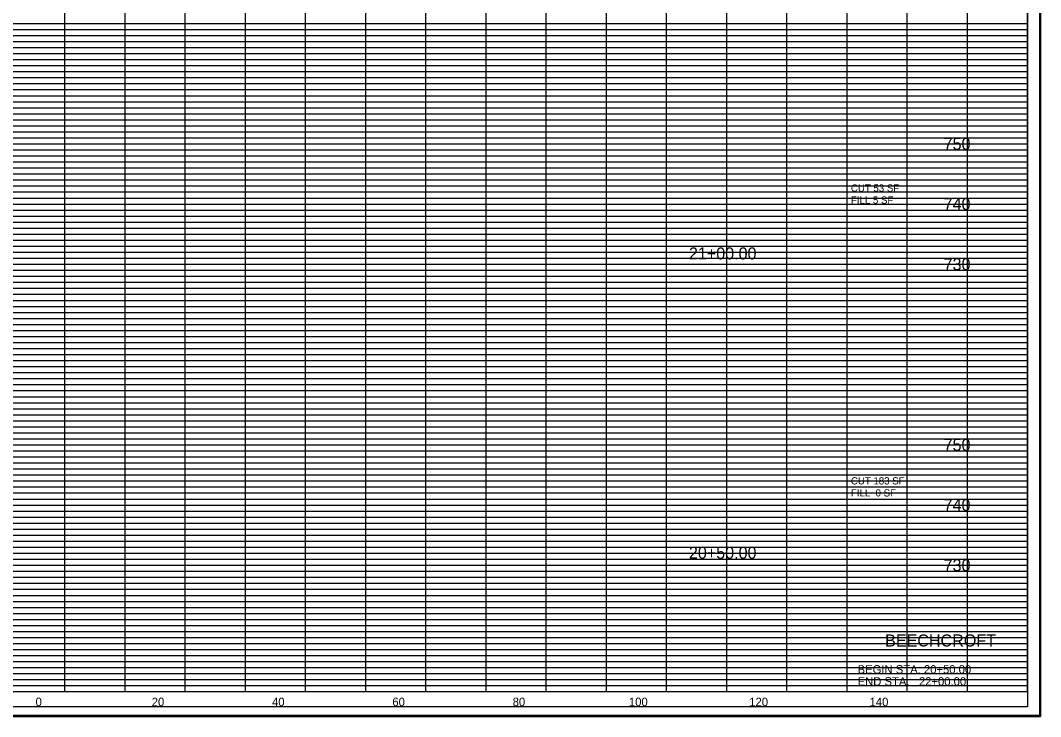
# Model space of a CAD drawing. Extents: x -200 to 1704, y -325 to 2307.
# Drawn here: x 1532.6 to 1702.2, y 995.9 to 1111.5 of the extents above; entities that cross this region are included whole.
import ezdxf

# ---------------------------------------------------------------- set-up
doc = ezdxf.new("R2010")
doc.units = 0
for name, color, linetype in [('DESIGN - SHEET - Corner Text', 7, 'Continuous'), ('DESIGN - SHEET - Light Grid', 7, 'Continuous'), ('DESIGN - SHEET - Linework', 7, 'Continuous'), ('DESIGN - SHEET - Plot Shape', 7, 'Continuous'), ('DESIGN - TYPICAL - Text', 7, 'Continuous')]:
    doc.layers.add(name, color=color, linetype=linetype)

msp = doc.modelspace()

# ---------------------------------------------------------------- linework, layer by layer
at = {"layer": 'DESIGN - SHEET - Light Grid'}
for p, q in [((1460, 1111), (1540, 1111)), ((1540, 1111), (1620, 1111)), ((1620, 1111), (1700, 1111)), ((1460, 1109), (1540, 1109)), ((1460, 1108), (1540, 1108)), ((1540, 1109), (1620, 1109)), ((1540, 1108), (1620, 1108)), ((1620, 1109), (1700, 1109)), ((1620, 1108), (1700, 1108)), ((1460, 1107), (1540, 1107)), ((1460, 1106), (1540, 1106)), ((1540, 1107), (1620, 1107)), ((1540, 1106), (1620, 1106)), ((1620, 1107), (1700, 1107)), ((1620, 1106), (1700, 1106)), ((1460, 1105), (1540, 1105)), ((1460, 1104), (1540, 1104)), ((1540, 1105), (1620, 1105)), ((1540, 1104), (1620, 1104)), ((1620, 1105), (1700, 1105)), ((1620, 1104), (1700, 1104)), ((1460, 1103), (1540, 1103)), ((1540, 1103), (1620, 1103)), ((1620, 1103), (1700, 1103)), ((1460, 1102), (1540, 1102)), ((1460, 1101), (1540, 1101)), ((1540, 1102), (1620, 1102)), ((1540, 1101), (1620, 1101)), ((1620, 1102), (1700, 1102)), ((1620, 1101), (1700, 1101)), ((1460, 1099), (1540, 1099)), ((1540, 1099), (1620, 1099)), ((1620, 1099), (1700, 1099)), ((1460, 1098), (1540, 1098)), ((1540, 1098), (1620, 1098)), ((1620, 1098), (1700, 1098)), ((1460, 1097), (1540, 1097)), ((1460, 1096), (1540, 1096)), ((1540, 1097), (1620, 1097)), ((1540, 1096), (1620, 1096)), ((1620, 1097), (1700, 1097)), ((1620, 1096), (1700, 1096)), ((1460, 1095), (1540, 1095)), ((1460, 1094), (1540, 1094)), ((1540, 1095), (1620, 1095)), ((1540, 1094), (1620, 1094)), ((1620, 1095), (1700, 1095)), ((1620, 1094), (1700, 1094)), ((1460, 1093), (1540, 1093)), ((1540, 1093), (1620, 1093)), ((1620, 1093), (1700, 1093)), ((1460, 1092), (1540, 1092)), ((1460, 1091), (1540, 1091)), ((1540, 1092), (1620, 1092)), ((1540, 1091), (1620, 1091)), ((1620, 1092), (1700, 1092)), ((1620, 1091), (1700, 1091)), ((1460, 1089), (1540, 1089)), ((1540, 1089), (1620, 1089)), ((1620, 1089), (1700, 1089)), ((1460, 1088), (1540, 1088)), ((1540, 1088), (1620, 1088)), ((1620, 1088), (1700, 1088)), ((1460, 1087), (1540, 1087)), ((1460, 1086), (1540, 1086)), ((1540, 1087), (1620, 1087)), ((1540, 1086), (1620, 1086)), ((1620, 1087), (1700, 1087)), ((1620, 1086), (1700, 1086)), ((1460, 1085), (1540, 1085)), ((1460, 1084), (1540, 1084)), ((1540, 1085), (1620, 1085)), ((1540, 1084), (1620, 1084)), ((1620, 1085), (1700, 1085)), ((1620, 1084), (1700, 1084)), ((1460, 1083), (1540, 1083)), ((1460, 1082), (1540, 1082)), ((1540, 1083), (1620, 1083)), ((1540, 1082), (1620, 1082)), ((1620, 1083), (1700, 1083)), ((1620, 1082), (1700, 1082)), ((1460, 1081), (1540, 1081)), ((1540, 1081), (1620, 1081)), ((1620, 1081), (1700, 1081)), ((1460, 1079), (1540, 1079)), ((1540, 1079), (1620, 1079)), ((1620, 1079), (1700, 1079)), ((1460, 1078), (1540, 1078)), ((1460, 1077), (1540, 1077)), ((1540, 1078), (1620, 1078)), ((1540, 1077), (1620, 1077)), ((1620, 1078), (1700, 1078)), ((1620, 1077), (1700, 1077)), ((1460, 1076), (1540, 1076)), ((1540, 1076), (1620, 1076)), ((1620, 1076), (1700, 1076)), ((1460, 1075), (1540, 1075)), ((1460, 1074), (1540, 1074)), ((1540, 1075), (1620, 1075)), ((1540, 1074), (1620, 1074)), ((1620, 1075), (1700, 1075)), ((1620, 1074), (1700, 1074)), ((1460, 1073), (1540, 1073)), ((1460, 1072), (1540, 1072)), ((1540, 1073), (1620, 1073)), ((1540, 1072), (1620, 1072)), ((1620, 1073), (1700, 1073)), ((1620, 1072), (1700, 1072)), ((1460, 1071), (1540, 1071)), ((1540, 1071), (1620, 1071)), ((1620, 1071), (1700, 1071)), ((1460, 1069), (1540, 1069)), ((1540, 1069), (1620, 1069)), ((1620, 1069), (1700, 1069)), ((1460, 1068), (1540, 1068)), ((1460, 1067), (1540, 1067)), ((1540, 1068), (1620, 1068)), ((1540, 1067), (1620, 1067)), ((1620, 1068), (1700, 1068)), ((1620, 1067), (1700, 1067)), ((1460, 1066), (1540, 1066)), ((1460, 1065), (1540, 1065)), ((1540, 1066), (1620, 1066)), ((1540, 1065), (1620, 1065)), ((1620, 1066), (1700, 1066)), ((1620, 1065), (1700, 1065)), ((1460, 1064), (1540, 1064)), ((1540, 1064), (1620, 1064)), ((1620, 1064), (1700, 1064)), ((1460, 1063), (1540, 1063)), ((1460, 1062), (1540, 1062)), ((1540, 1063), (1620, 1063)), ((1540, 1062), (1620, 1062)), ((1620, 1063), (1700, 1063)), ((1620, 1062), (1700, 1062)), ((1460, 1061), (1540, 1061)), ((1540, 1061), (1620, 1061)), ((1620, 1061), (1700, 1061)), ((1460, 1059), (1540, 1059)), ((1540, 1059), (1620, 1059)), ((1620, 1059), (1700, 1059)), ((1460, 1058), (1540, 1058)), ((1460, 1057), (1540, 1057)), ((1540, 1058), (1620, 1058)), ((1540, 1057), (1620, 1057)), ((1620, 1058), (1700, 1058)), ((1620, 1057), (1700, 1057)), ((1460, 1056), (1540, 1056)), ((1460, 1055), (1540, 1055)), ((1540, 1056), (1620, 1056)), ((1540, 1055), (1620, 1055)), ((1620, 1056), (1700, 1056)), ((1620, 1055), (1700, 1055)), ((1460, 1054), (1540, 1054)), ((1540, 1054), (1620, 1054)), ((1620, 1054), (1700, 1054)), ((1460, 1053), (1540, 1053)), ((1460, 1052), (1540, 1052)), ((1540, 1053), (1620, 1053)), ((1540, 1052), (1620, 1052)), ((1620, 1053), (1700, 1053)), ((1620, 1052), (1700, 1052)), ((1460, 1051), (1540, 1051)), ((1540, 1051), (1620, 1051)), ((1620, 1051), (1700, 1051)), ((1460, 1049), (1540, 1049)), ((1540, 1049), (1620, 1049)), ((1620, 1049), (1700, 1049)), ((1460, 1048), (1540, 1048)), ((1460, 1047), (1540, 1047)), ((1540, 1048), (1620, 1048)), ((1540, 1047), (1620, 1047)), ((1620, 1048), (1700, 1048)), ((1620, 1047), (1700, 1047)), ((1460, 1046), (1540, 1046)), ((1460, 1045), (1540, 1045)), ((1540, 1046), (1620, 1046)), ((1540, 1045), (1620, 1045)), ((1620, 1046), (1700, 1046)), ((1620, 1045), (1700, 1045)), ((1460, 1044), (1540, 1044)), ((1460, 1043), (1540, 1043)), ((1540, 1044), (1620, 1044)), ((1540, 1043), (1620, 1043)), ((1620, 1044), (1700, 1044)), ((1620, 1043), (1700, 1043)), ((1460, 1042), (1540, 1042)), ((1540, 1042), (1620, 1042)), ((1620, 1042), (1700, 1042)), ((1460, 1041), (1540, 1041)), ((1540, 1041), (1620, 1041)), ((1620, 1041), (1700, 1041)), ((1460, 1039), (1540, 1039)), ((1460, 1038), (1540, 1038)), ((1540, 1039), (1620, 1039)), ((1540, 1038), (1620, 1038)), ((1620, 1039), (1700, 1039)), ((1620, 1038), (1700, 1038)), ((1460, 1037), (1540, 1037)), ((1540, 1037), (1620, 1037)), ((1620, 1037), (1700, 1037)), ((1460, 1036), (1540, 1036)), ((1460, 1035), (1540, 1035)), ((1540, 1036), (1620, 1036)), ((1540, 1035), (1620, 1035)), ((1620, 1036), (1700, 1036)), ((1620, 1035), (1700, 1035)), ((1460, 1034), (1540, 1034)), ((1460, 1033), (1540, 1033)), ((1540, 1034), (1620, 1034)), ((1540, 1033), (1620, 1033)), ((1620, 1034), (1700, 1034)), ((1620, 1033), (1700, 1033)), ((1460, 1032), (1540, 1032)), ((1540, 1032), (1620, 1032)), ((1620, 1032), (1700, 1032)), ((1460, 1031), (1540, 1031)), ((1540, 1031), (1620, 1031)), ((1620, 1031), (1700, 1031)), ((1460, 1029), (1540, 1029)), ((1460, 1028), (1540, 1028)), ((1540, 1029), (1620, 1029)), ((1540, 1028), (1620, 1028)), ((1620, 1029), (1700, 1029)), ((1620, 1028), (1700, 1028)), ((1460, 1027), (1540, 1027)), ((1460, 1026), (1540, 1026)), ((1540, 1027), (1620, 1027)), ((1540, 1026), (1620, 1026)), ((1620, 1027), (1700, 1027)), ((1620, 1026), (1700, 1026)), ((1460, 1025), (1540, 1025)), ((1540, 1025), (1620, 1025)), ((1620, 1025), (1700, 1025)), ((1460, 1024), (1540, 1024)), ((1460, 1023), (1540, 1023)), ((1540, 1024), (1620, 1024)), ((1540, 1023), (1620, 1023)), ((1620, 1024), (1700, 1024)), ((1620, 1023), (1700, 1023)), ((1460, 1022), (1540, 1022)), ((1460, 1021), (1540, 1021)), ((1540, 1022), (1620, 1022)), ((1540, 1021), (1620, 1021)), ((1620, 1022), (1700, 1022)), ((1620, 1021), (1700, 1021)), ((1460, 1019), (1540, 1019)), ((1460, 1018), (1540, 1018)), ((1540, 1019), (1620, 1019)), ((1540, 1018), (1620, 1018)), ((1620, 1019), (1700, 1019)), ((1620, 1018), (1700, 1018)), ((1460, 1017), (1540, 1017)), ((1460, 1016), (1540, 1016)), ((1540, 1017), (1620, 1017)), ((1540, 1016), (1620, 1016)), ((1620, 1017), (1700, 1017)), ((1620, 1016), (1700, 1016)), ((1460, 1015), (1540, 1015)), ((1540, 1015), (1620, 1015)), ((1620, 1015), (1700, 1015)), ((1460, 1014), (1540, 1014)), ((1460, 1013), (1540, 1013)), ((1540, 1014), (1620, 1014)), ((1540, 1013), (1620, 1013)), ((1620, 1014), (1700, 1014)), ((1620, 1013), (1700, 1013)), ((1460, 1012), (1540, 1012)), ((1460, 1011), (1540, 1011)), ((1540, 1012), (1620, 1012)), ((1540, 1011), (1620, 1011)), ((1620, 1012), (1700, 1012)), ((1620, 1011), (1700, 1011)), ((1460, 1009), (1540, 1009)), ((1460, 1008), (1540, 1008)), ((1540, 1009), (1620, 1009)), ((1540, 1008), (1620, 1008)), ((1620, 1009), (1700, 1009)), ((1620, 1008), (1700, 1008)), ((1460, 1007), (1540, 1007)), ((1460, 1006), (1540, 1006)), ((1540, 1007), (1620, 1007)), ((1540, 1006), (1620, 1006)), ((1620, 1007), (1700, 1007)), ((1620, 1006), (1700, 1006)), ((1460, 1005), (1540, 1005)), ((1460, 1004), (1540, 1004)), ((1540, 1005), (1620, 1005)), ((1540, 1004), (1620, 1004)), ((1620, 1005), (1700, 1005)), ((1620, 1004), (1700, 1004)), ((1460, 1003), (1540, 1003)), ((1540, 1003), (1620, 1003)), ((1620, 1003), (1700, 1003)), ((1460, 1002), (1540, 1002)), ((1460, 1001), (1540, 1001)), ((1540, 1002), (1620, 1002)), ((1540, 1001), (1620, 1001)), ((1620, 1002), (1700, 1002)), ((1620, 1001), (1700, 1001))]:
    msp.add_line(p, q, dxfattribs=at)
at = {"layer": 'DESIGN - SHEET - Linework'}
for p, q in [((1702.17, 1214.14), (1702.17, 995.86)), ((1540, 1000), (1540, 1210)), ((1550, 1000), (1550, 1210)), ((1560, 1000), (1560, 1210)), ((1570, 1000), (1570, 1210)), ((1580, 1000), (1580, 1210)), ((1590, 1000), (1590, 1210)), ((1600, 1000), (1600, 1210)), ((1610, 1000), (1610, 1210)), ((1620, 1000), (1620, 1210)), ((1630, 1000), (1630, 1210)), ((1640, 1000), (1640, 1210)), ((1650, 1000), (1650, 1210)), ((1660, 1000), (1660, 1200)), ((1670, 1000), (1670, 1200)), ((1680, 1000), (1680, 1200)), ((1690, 1000), (1690, 1200)), ((1380, 1110), (1700, 1110)), ((1380, 1100), (1700, 1100)), ((1380, 1090), (1700, 1090)), ((1380, 1080), (1700, 1080)), ((1380, 1070), (1700, 1070)), ((1380, 1060), (1700, 1060)), ((1380, 1050), (1700, 1050)), ((1380, 1040), (1700, 1040)), ((1380, 1030), (1700, 1030)), ((1380, 1020), (1700, 1020)), ((1380, 1010), (1700, 1010)), ((1361.77, 995.86), (1702.17, 995.86))]:
    msp.add_line(p, q, dxfattribs=at)
msp.add_lwpolyline([(1380, 1210), (1380, 1000), (1700, 1000), (1700, 1210), (1380, 1210)], dxfattribs=at)
at = {"layer": 'DESIGN - SHEET - Plot Shape'}
for points in [[(1361.97, 1213.94), (1701.97, 1213.94), (1701.97, 996.06), (1361.97, 996.06)], [(1371.5, 1210), (1700, 1210), (1700, 997.5), (1371.5, 997.5)]]:
    msp.add_lwpolyline(points, close=True, dxfattribs=at)

# ---------------------------------------------------------------- texts
at = {"layer": 'DESIGN - SHEET - Corner Text'}
for s, height, p in [('BEECHCROFT ', 2, (1676.33, 1007.5)), ('BEGIN STA. 20+50.00', 1.4, (1671.75, 1003)), ('END STA.   22+00.00', 1.4, (1671.75, 1001))]:
    msp.add_text(s, height=height, dxfattribs=at).set_placement(p)
at = {"layer": 'DESIGN - TYPICAL - Text'}
for s, height, p in [('     750     ', 2, (1682.34, 1090)), ('CUT 53 SF', 1.2, (1670.64, 1083.06)), ('FILL 5 SF', 1.2, (1670.64, 1081.06)), ('     740     ', 2, (1682.34, 1080)), ('     21+00.00     ', 2, (1640, 1071.8)), ('     730     ', 2, (1682.34, 1070)), ('     750     ', 2, (1682.34, 1040)), ('CUT 183 SF', 1.2, (1670.64, 1034.42)), ('FILL  0 SF', 1.2, (1670.64, 1032.42)), ('     740     ', 2, (1682.34, 1030)), ('     20+50.00     ', 2, (1640, 1022.08)), ('     730     ', 2, (1682.34, 1020)), ('     0     ', 1.4, (1532.51, 997.6)), ('     20     ', 1.4, (1551.82, 997.6)), ('     40     ', 1.4, (1571.82, 997.6)), ('     60     ', 1.4, (1591.82, 997.6)), ('     80     ', 1.4, (1611.82, 997.6)), ('     100     ', 1.4, (1631.14, 997.6)), ('     120     ', 1.4, (1651.14, 997.6)), ('     140     ', 1.4, (1671.14, 997.6))]:
    msp.add_text(s, height=height, dxfattribs=at).set_placement(p)

doc.saveas('drawing.dxf')
